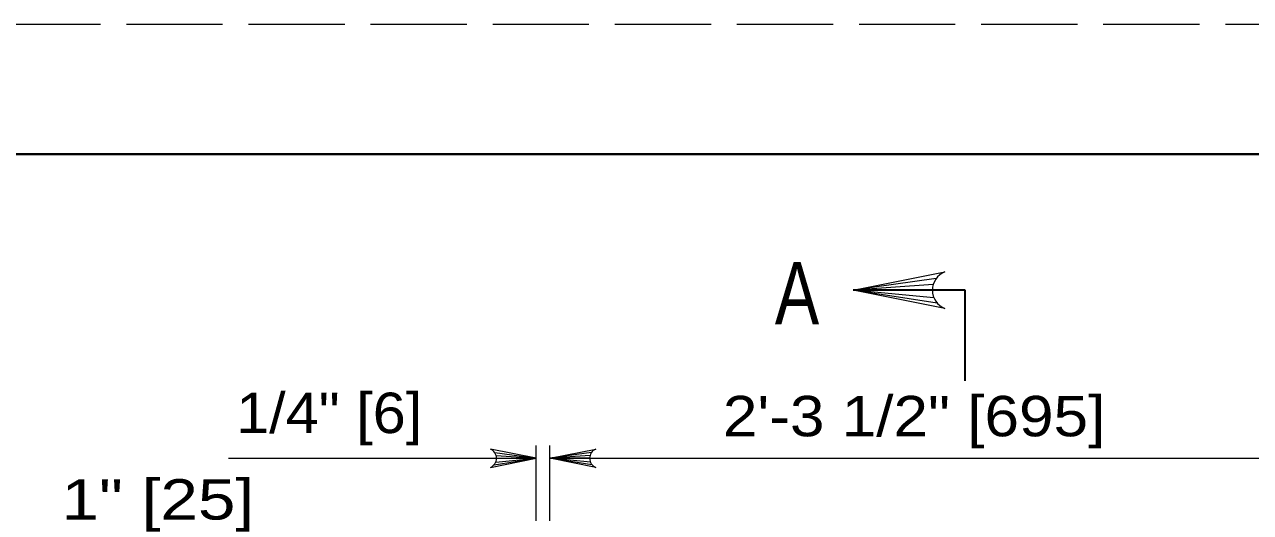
# Model space of a CAD drawing. Extents: x -410.5 to -376.5, y 1617.6 to 1661.6.
# Drawn here: x -396.1 to -391.362, y 1659.678 to 1661.562 of the extents above; entities that cross this region are included whole.
import ezdxf

# ---------------------------------------------------------------- set-up
doc = ezdxf.new("R2010")
doc.units = 0
doc.header["$LTSCALE"] = 0.062
doc.linetypes.add('LONG_DASHED', pattern=[7.5, 6, -1.5])
doc.layers.add('1', color=7, linetype='Continuous', lineweight=13)

msp = doc.modelspace()

# ---------------------------------------------------------------- linework, layer by layer
at = {"layer": '1', "lineweight": 25}
msp.add_line((-408.45475, 1661.06183), (-376.95475, 1661.06183), dxfattribs=at)
at = {"layer": '1'}
for p, q in [((-392.57667, 1660.58083), (-392.89717, 1660.536)), ((-392.5875, 1660.55867), (-392.89717, 1660.536)), ((-392.59083, 1660.536), (-392.89717, 1660.536)), ((-392.58517, 1660.50725), (-392.89717, 1660.536)), ((-392.57283, 1660.4865), (-392.89717, 1660.536)), ((-394.28308, 1659.90942), (-394.12283, 1659.887)), ((-394.12283, 1658.80683), (-394.12283, 1659.937)), ((-394.06925, 1658.80683), (-394.06925, 1659.937)), ((-393.909, 1659.90942), (-394.06925, 1659.887)), ((-395.31167, 1659.887), (-394.12283, 1659.887)), ((-394.285, 1659.86225), (-394.12283, 1659.887)), ((-394.27883, 1659.87258), (-394.12283, 1659.887)), ((-394.27767, 1659.89833), (-394.12283, 1659.887)), ((-394.276, 1659.887), (-394.12283, 1659.887)), ((-393.91442, 1659.89833), (-394.06925, 1659.887)), ((-394.06925, 1659.887), (-392.77792, 1659.887)), ((-393.91608, 1659.887), (-394.06925, 1659.887)), ((-393.91325, 1659.87258), (-394.06925, 1659.887)), ((-393.90717, 1659.86225), (-394.06925, 1659.887)), ((-392.77792, 1659.887), (-390.85967, 1659.887)), ((-392.03408, 1659.887), (-390.86258, 1659.887))]:
    msp.add_line(p, q, dxfattribs=at)
at = {"layer": '1', "lineweight": 35}
for p, q in [((-392.4645, 1660.536), (-392.89717, 1660.536)), ((-392.4645, 1660.18675), (-392.4645, 1660.536))]:
    msp.add_line(p, q, dxfattribs=at)
at = {"layer": '1', "linetype": 'LONG_DASHED'}
msp.add_lwpolyline([(-410.45475, 1639.56183), (-376.45475, 1639.56183), (-376.45475, 1661.56183), (-410.45475, 1661.56183)], close=True, dxfattribs=at)
at = {"layer": '1', "lineweight": 40}
msp.add_lwpolyline([(-408.45475, 1661.06183), (-376.95475, 1661.06183), (-376.95475, 1640.06183), (-408.45475, 1640.06183)], close=True, dxfattribs=at)
msp.add_lwpolyline([(-408.45475, 1661.06183), (-376.95475, 1661.06183), (-376.95475, 1640.06183), (-408.45475, 1640.06183)], close=True, dxfattribs=at)
at = {"layer": '1'}
for points in [[(-392.54317, 1660.46525), (-392.89717, 1660.536), (-392.54317, 1660.60683)], [(-394.29983, 1659.85158), (-394.12283, 1659.887), (-394.29983, 1659.92242)], [(-393.89225, 1659.85158), (-394.06925, 1659.887), (-393.89225, 1659.92242)]]:
    msp.add_lwpolyline(points, dxfattribs=at)
for centre, radius, start, end in [((-392.51454, 1660.53611), 0.0764, 112.08782, 247.91395), ((-394.31413, 1659.88703), 0.0382, 292.08605, 67.91218), ((-393.87797, 1659.88703), 0.0382, 112.08782, 247.91395)]:
    msp.add_arc(centre, radius, start, end, dxfattribs=at)

# ---------------------------------------------------------------- texts
for s, height, width, p in [('A', 0.24, 0.8, (-393.20008, 1660.40467)), ('1/4" [6]', 0.156, 1.1, (-395.28233, 1659.98442)), ('2\'-3 1/2" [695]', 0.156, 1.15, (-393.40083, 1659.97208)), ('1" [25]', 0.156, 1.25, (-395.95758, 1659.65042))]:
    msp.add_text(s, height=height, dxfattribs=dict(at, width=width)).set_placement(p)

doc.saveas('drawing.dxf')
